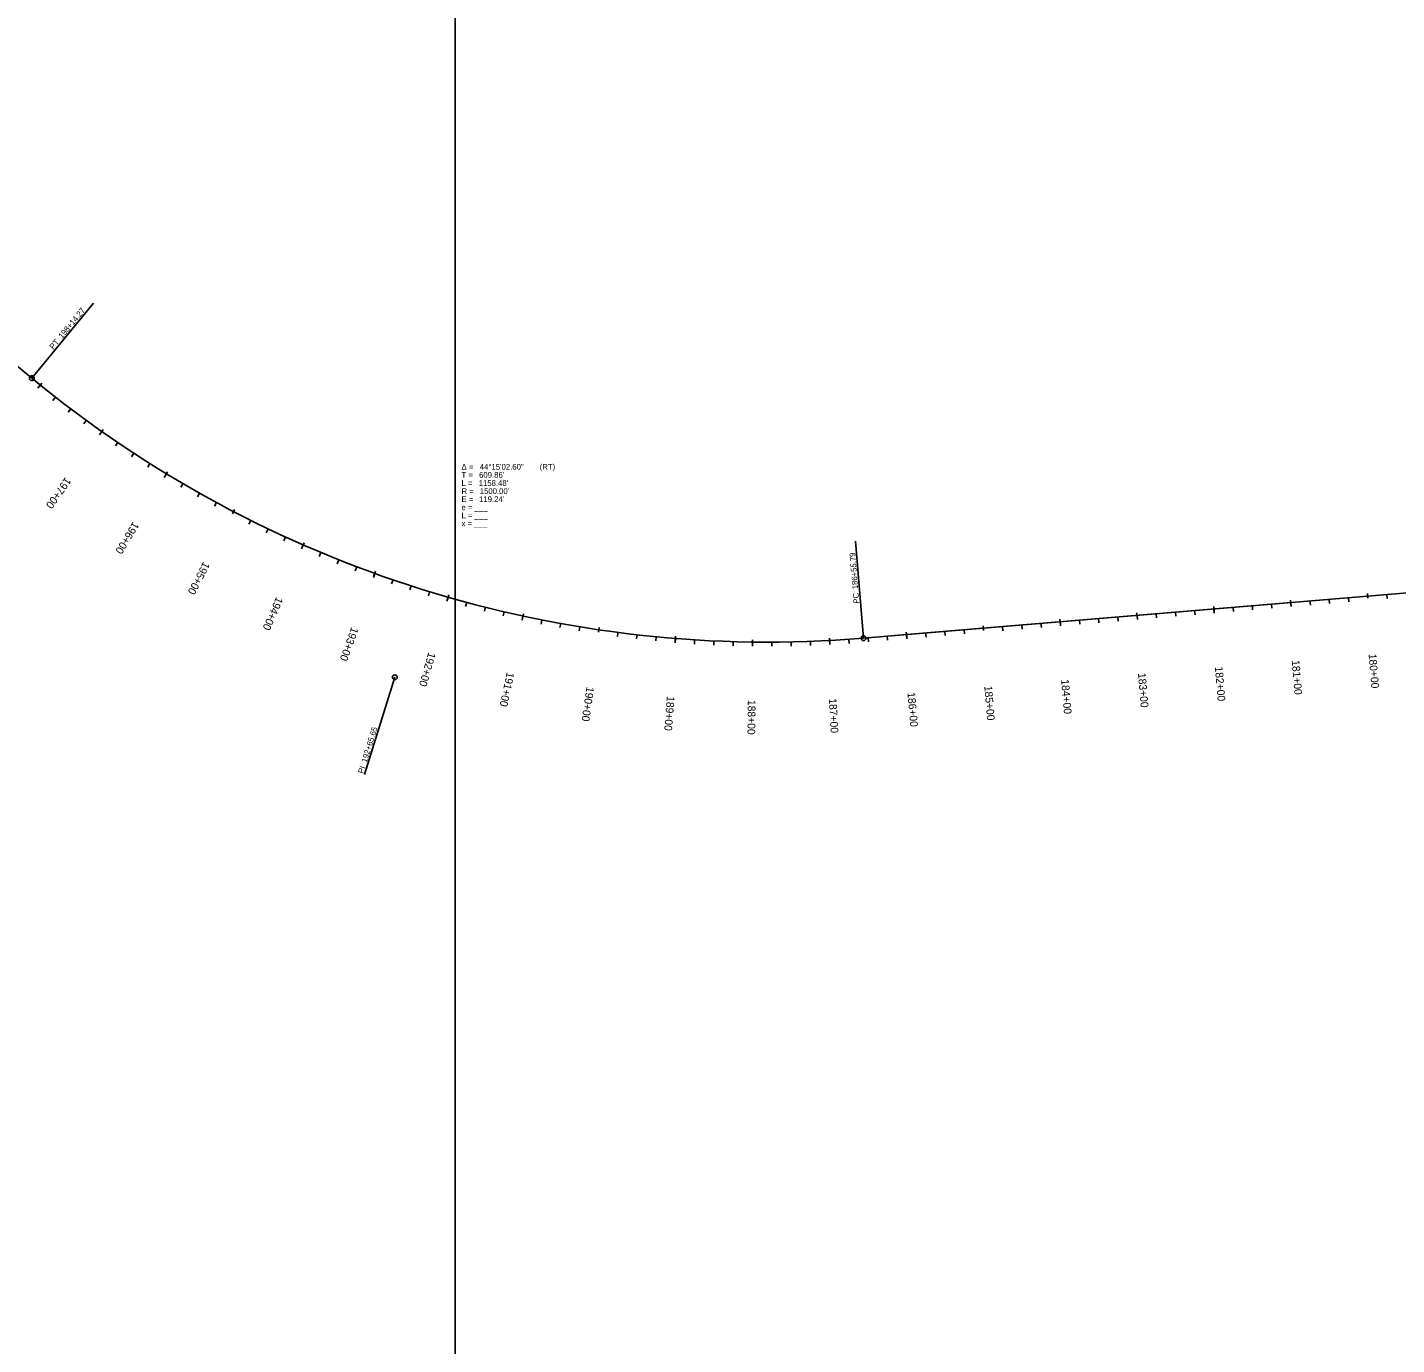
# Model space of a CAD drawing. Extents: x 5226274 to 5237131, y 3641705 to 3648830.
# Drawn here: x 5228961 to 5230736, y 3645314 to 3647021 of the extents above; entities that cross this region are included whole.
import ezdxf

# ---------------------------------------------------------------- set-up
doc = ezdxf.new("R2010")
doc.units = 0
for name, color, linetype in [('Alignment', 7, 'Continuous'), ('TextAlignment', 7, 'Continuous'), ('TextAlignmentLrg', 7, 'Continuous'), ('TextAlignmentSml', 7, 'Continuous'), ('TextNonPlot', 7, 'Continuous')]:
    doc.layers.add(name, color=color, linetype=linetype)

msp = doc.modelspace()

# ---------------------------------------------------------------- linework, layer by layer
at = {"layer": 'Alignment'}
for p, q in [((5228966.5, 3646566.3), (5226341.7, 3648728.2)), ((5231876.8, 3646382.3), (5230085.3, 3646232.7)), ((5231058.4, 3646314), (5230044.9, 3646229.3))]:
    msp.add_line(p, q, dxfattribs=at)
msp.add_arc((5229920.1, 3647724.1), 1500, 230.5226, 274.7733, dxfattribs=at)
msp.add_arc((5229920.1, 3647724.1), 1500, 230.5226, 274.7733, dxfattribs=at)
at = {"layer": 'TextAlignment'}
for p, q in [((5228966.5, 3646566.3), (5229046.6, 3646663.6)), ((5229046.6, 3646663.6), (5229046.6, 3646663.6)), ((5230044.9, 3646229.3), (5230034.5, 3646354.9)), ((5230034.5, 3646354.9), (5230034.5, 3646354.9)), ((5229437.2, 3646178.6), (5229397.8, 3646052.6)), ((5229397.8, 3646052.6), (5229397.8, 3646052.6))]:
    msp.add_line(p, q, dxfattribs=at)
for centre in [(5228966.5, 3646566.3), (5230044.9, 3646229.3), (5229437.2, 3646178.6)]:
    msp.add_circle(centre, 3.12, dxfattribs=at)
at = {"layer": 'TextAlignmentLrg'}
for p, q in [((5228977.5, 3646557.3), (5228974.1, 3646553.1)), ((5229057.3, 3646497.1), (5229054.2, 3646492.6)), ((5229141, 3646442.3), (5229138.2, 3646437.7)), ((5229226.7, 3646390.6), (5229229.5, 3646396)), ((5229318.3, 3646350.1), (5229316.1, 3646345.1)), ((5229411.2, 3646313.1), (5229409.3, 3646308)), ((5229506.3, 3646282.3), (5229504.8, 3646277.1)), ((5230598.8, 3646275.6), (5230599.2, 3646270.1)), ((5230698.7, 3646280.9), (5230698.2, 3646287)), ((5229603.3, 3646258), (5229602.1, 3646252.6)), ((5230399.5, 3646258.9), (5230399.9, 3646253.5)), ((5230499.1, 3646267.3), (5230499.6, 3646261.8)), ((5229701.2, 3646237.1), (5229702.1, 3646243.2)), ((5230200.4, 3646239.2), (5230199.9, 3646245.3)), ((5230299.8, 3646250.6), (5230300.3, 3646245.2)), ((5229801, 3646228.9), (5229800.6, 3646223.4)), ((5229900.9, 3646224.3), (5229900.8, 3646218.8)), ((5230000.8, 3646226.3), (5230001.1, 3646220.9)), ((5230100.5, 3646234), (5230101, 3646228.5))]:
    msp.add_line(p, q, dxfattribs=at)
at = {"layer": 'TextAlignmentSml'}
for p, q in [((5228975.6, 3646554.9), (5228979.4, 3646559.7)), ((5228997.1, 3646541.8), (5228993.7, 3646537.4)), ((5229016.9, 3646526.5), (5229013.6, 3646522.2)), ((5229037, 3646511.6), (5229033.8, 3646507.2)), ((5229055.6, 3646494.6), (5229059.1, 3646499.6)), ((5229077.9, 3646482.9), (5229074.8, 3646478.4)), ((5229098.7, 3646469), (5229095.7, 3646464.5)), ((5229119.7, 3646455.5), (5229116.8, 3646450.9)), ((5229139.4, 3646439.7), (5229142.6, 3646445)), ((5229162.5, 3646429.5), (5229159.7, 3646424.8)), ((5229184.1, 3646417.1), (5229181.5, 3646412.3)), ((5229206, 3646405), (5229203.4, 3646400.2)), ((5229226.7, 3646390.6), (5229229.5, 3646396)), ((5229250.4, 3646381.9), (5229247.9, 3646377.1)), ((5229272.8, 3646371), (5229270.5, 3646366)), ((5229295.5, 3646360.4), (5229293.2, 3646355.4)), ((5229317.1, 3646347.3), (5229319.5, 3646353)), ((5229341.3, 3646340.3), (5229339.2, 3646335.3)), ((5229364.4, 3646330.9), (5229362.4, 3646325.8)), ((5229387.7, 3646321.8), (5229385.8, 3646316.7)), ((5229410.1, 3646310.2), (5229412.2, 3646316)), ((5229434.8, 3646304.8), (5229433, 3646299.7)), ((5229458.5, 3646296.9), (5229456.8, 3646291.7)), ((5229482.3, 3646289.4), (5229480.7, 3646284.2)), ((5229505.5, 3646279.4), (5229507.1, 3646285.3)), ((5229530.4, 3646275.6), (5229529, 3646270.4)), ((5230573.9, 3646273.5), (5230574.3, 3646268.1)), ((5230599, 3646272.5), (5230598.5, 3646278.6)), ((5230623.7, 3646277.7), (5230624.2, 3646272.2)), ((5230648.6, 3646279.7), (5230649.1, 3646274.3)), ((5230673.5, 3646281.8), (5230674, 3646276.4)), ((5230698.7, 3646280.9), (5230698.2, 3646287)), ((5230723.4, 3646286), (5230723.8, 3646280.5)), ((5229554.6, 3646269.4), (5229553.3, 3646264.1)), ((5229578.9, 3646263.5), (5229577.6, 3646258.1)), ((5229602.6, 3646255), (5229603.9, 3646261)), ((5230349.7, 3646254.8), (5230350.1, 3646249.3)), ((5230374.6, 3646256.9), (5230375, 3646251.4)), ((5230399.7, 3646255.9), (5230399.2, 3646262)), ((5230424.4, 3646261), (5230424.9, 3646255.6)), ((5230449.3, 3646263.1), (5230449.8, 3646257.7)), ((5230474.2, 3646265.2), (5230474.7, 3646259.7)), ((5230499.4, 3646264.2), (5230498.9, 3646270.3)), ((5230524.1, 3646269.3), (5230524.5, 3646263.9)), ((5230549, 3646271.4), (5230549.4, 3646266)), ((5229627.7, 3646252.9), (5229626.7, 3646247.5)), ((5229652.3, 3646248.2), (5229651.3, 3646242.9)), ((5229676.9, 3646244), (5229676.1, 3646238.6)), ((5229701.2, 3646237.1), (5229702.1, 3646243.2)), ((5229726.4, 3646236.7), (5229725.7, 3646231.3)), ((5230100.8, 3646230.9), (5230100.3, 3646237)), ((5230150.4, 3646238.1), (5230150.8, 3646232.7)), ((5230175.3, 3646240.2), (5230175.7, 3646234.8)), ((5230200.4, 3646239.2), (5230199.9, 3646245.3)), ((5230225.1, 3646244.4), (5230225.5, 3646238.9)), ((5230250, 3646246.5), (5230250.5, 3646241)), ((5230274.9, 3646248.5), (5230275.4, 3646243.1)), ((5230300.1, 3646247.6), (5230299.6, 3646253.7)), ((5230324.7, 3646252.7), (5230325.2, 3646247.3)), ((5229751.2, 3646233.7), (5229750.6, 3646228.2)), ((5229776.1, 3646231.1), (5229775.6, 3646225.6)), ((5229800.7, 3646225.8), (5229801.2, 3646231.9)), ((5229825.9, 3646227.1), (5229825.6, 3646221.6)), ((5229850.9, 3646225.7), (5229850.6, 3646220.3)), ((5229875.9, 3646224.8), (5229875.7, 3646219.3)), ((5229900.8, 3646221.2), (5229900.9, 3646227.3)), ((5229925.9, 3646224.1), (5229925.9, 3646218.7)), ((5229950.9, 3646224.4), (5229951, 3646219)), ((5229975.9, 3646225.2), (5229976.1, 3646219.7)), ((5230001, 3646223.2), (5230000.7, 3646229.4)), ((5230025.8, 3646227.9), (5230026.2, 3646222.4)), ((5230050.7, 3646229.8), (5230051.2, 3646224.4)), ((5230075.6, 3646231.9), (5230076.1, 3646226.5)), ((5230125.4, 3646236.1), (5230125.9, 3646230.6))]:
    msp.add_line(p, q, dxfattribs=at)
at = {"layer": 'TextNonPlot'}
msp.add_lwpolyline([(5229515.6, 3647961.2), (5234567.8, 3647961.2), (5234567.8, 3643971.3), (5229515.6, 3643971.3)], close=True, dxfattribs=at)

# ---------------------------------------------------------------- texts
at = {"layer": 'TextAlignment'}
for s, rotation, p in [('198+14.27', 50.5226, (5229006, 3646616.9)), ('PT', 50.5226, (5228994.4, 3646602.9)), ('186+55.79', 94.7733, (5230038, 3646293)), ('PC', 94.7733, (5230039.5, 3646274.4)), ('192+65.65', 72.6479, (5229400.7, 3646067.4)), ('PI ', 72.6479, (5229396.3, 3646053.1))]:
    msp.add_text(s, height=7.5, rotation=rotation, dxfattribs=at).set_placement(p)
for s, p in [('Δ = ', (5229523.6, 3646447.6)), ('44°15\'02.60"', (5229547.3, 3646447.6)), (' (RT)', (5229622.2, 3646447.6)), ('T = ', (5229523.6, 3646437.1)), ('L = ', (5229523.6, 3646426.6)), ("1158.48'", (5229545.9, 3646426.6)), ("609.86'", (5229546.4, 3646437.1)), ('R = ', (5229523.6, 3646416.1)), ("1500.00'", (5229547.3, 3646416.1)), ('e = ___ ', (5229523.6, 3646395.1)), ('E = ', (5229523.6, 3646405.6)), ("119.24'", (5229546.4, 3646405.6)), ('x = ___', (5229523.6, 3646374.1)), ('L = ___', (5229523.6, 3646384.6))]:
    msp.add_text(s, height=7.5, dxfattribs=at).set_placement(p)
at = {"layer": 'TextAlignmentLrg'}
for s, rotation, p in [('195+00', 242.5267, (5229189.1, 3646329.1)), ('180+00', 274.7733, (5230699.7, 3646208.7)), ('190+00', 261.6253, (5229685.8, 3646166.7)), ('185+00', 274.7733, (5230201.4, 3646167.1))]:
    msp.add_text(s, height=10.02, rotation=rotation, dxfattribs=at).set_placement(p)
at = {"layer": 'TextAlignmentSml'}
for s, rotation, p in [('197+00', 234.8872, (5229010.1, 3646438.6)), ('196+00', 238.707, (5229097.8, 3646380.9)), ('195+00', 242.5267, (5229189.1, 3646329.1)), ('194+00', 246.3464, (5229283.6, 3646283.5)), ('193+00', 250.1661, (5229381, 3646244.3)), ('192+00', 253.9858, (5229480.8, 3646211.6)), ('180+00', 274.7733, (5230699.7, 3646208.7)), ('191+00', 257.8055, (5229582.5, 3646185.7)), ('182+00', 274.7733, (5230500.4, 3646192.1)), ('181+00', 274.7733, (5230600, 3646200.4)), ('190+00', 261.6253, (5229685.8, 3646166.7)), ('185+00', 274.7733, (5230201.4, 3646167.1)), ('184+00', 274.7733, (5230301.1, 3646175.5)), ('183+00', 274.7733, (5230400.7, 3646183.8)), ('189+00', 265.445, (5229790, 3646154.5)), ('188+00', 269.2647, (5229894.9, 3646149.3)), ('187+00', 273.0844, (5229999.9, 3646151.1)), ('186+00', 274.7733, (5230101.8, 3646158.8))]:
    msp.add_text(s, height=10.02, rotation=rotation, dxfattribs=at).set_placement(p)

doc.saveas('drawing.dxf')
